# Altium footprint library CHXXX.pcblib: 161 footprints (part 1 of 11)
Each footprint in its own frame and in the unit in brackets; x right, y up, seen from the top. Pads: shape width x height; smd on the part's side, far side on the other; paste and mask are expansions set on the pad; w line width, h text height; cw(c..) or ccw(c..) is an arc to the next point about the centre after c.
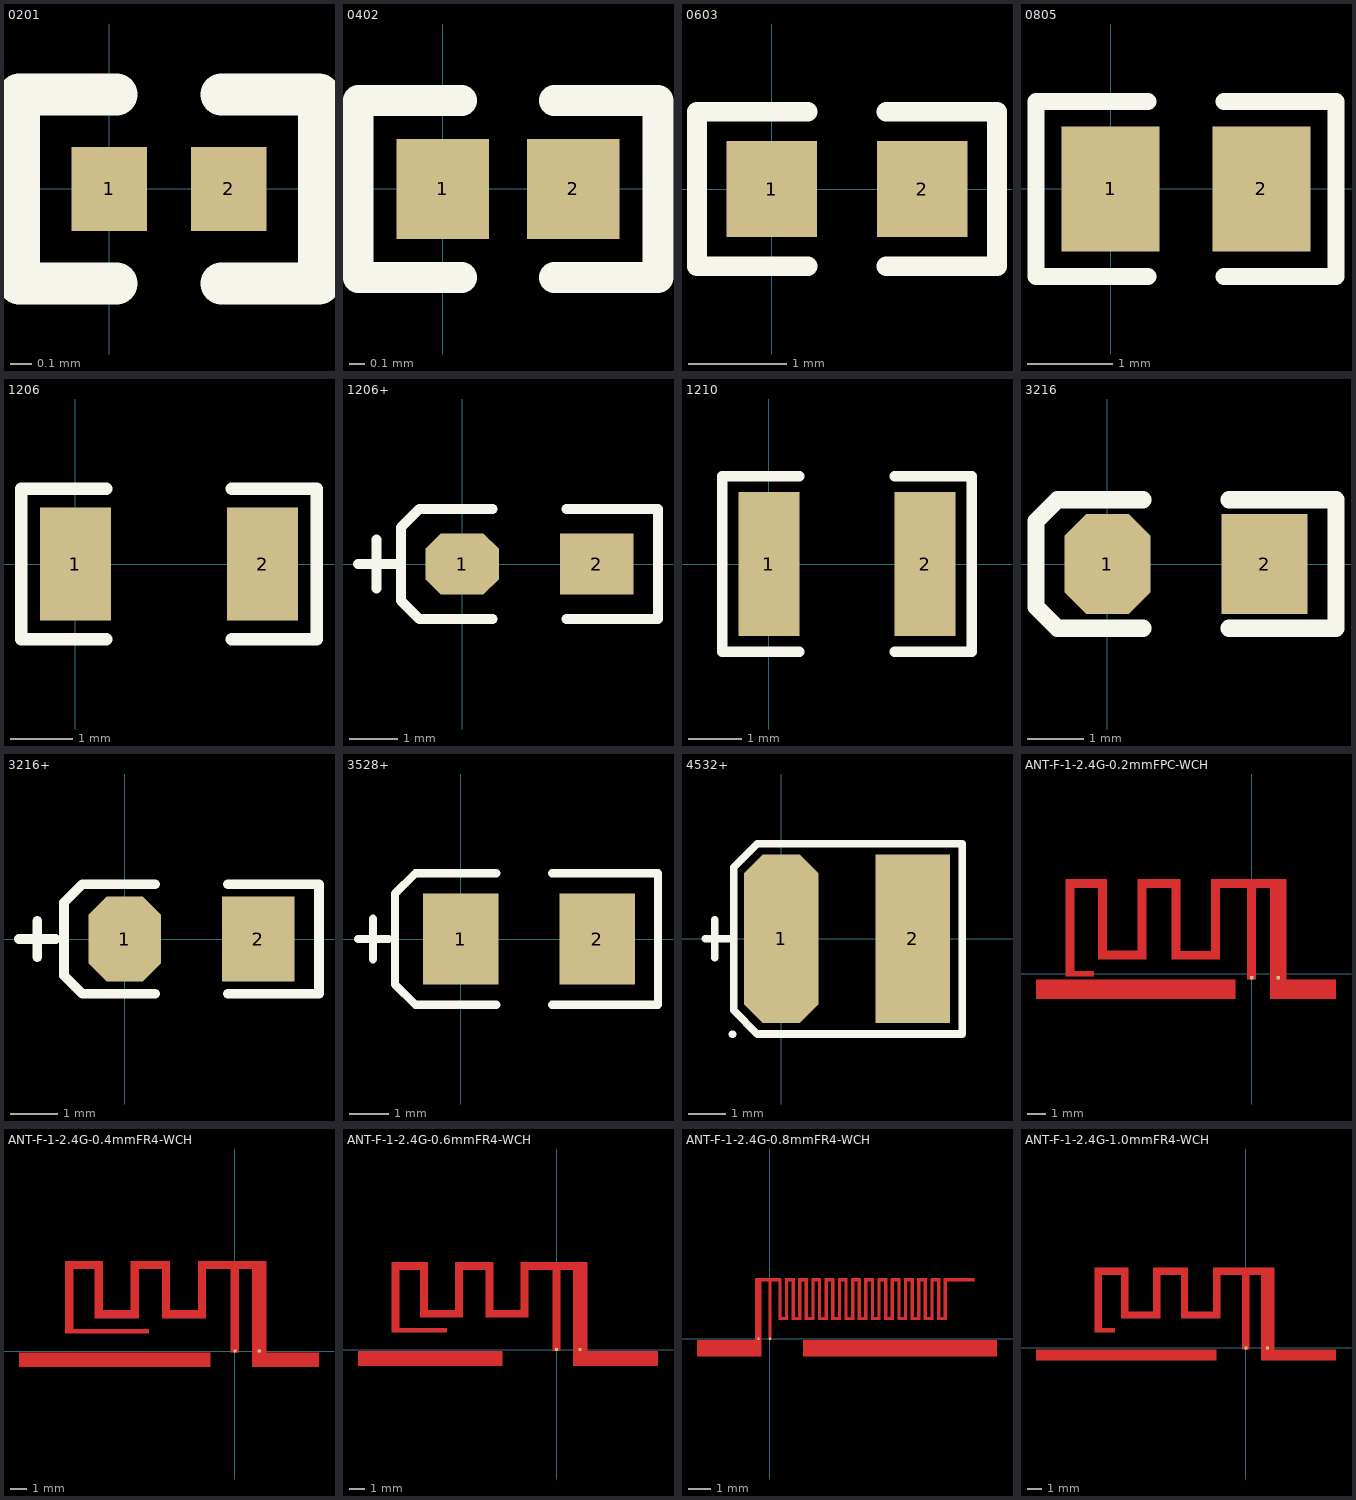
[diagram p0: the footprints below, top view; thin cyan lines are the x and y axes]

## 0201 [mm]
pads (2):
  rect 0.36x0.4 smd mask+0.051: 1(0,0) 2(0.57,0)
TopOverlay:
  lines w0.2: 0.035,-0.45 -0.43,-0.45 -0.43,0.45 0.035,0.45 ; 0.535,-0.45 1,-0.45 1,0.45 0.535,0.45

## 0402 [mm]
pads (2):
  rect 0.6x0.65 smd mask+0.051: 1(0,0) 2(0.85,0)
TopOverlay:
  lines w0.2: 0.125,-0.575 -0.55,-0.575 -0.55,0.575 0.125,0.575 ; 0.725,-0.575 1.4,-0.575 1.4,0.575 0.725,0.575

## 0603 [mm]
pads (2):
  rect 0.93x0.98 smd: 1(0,0) 2(1.54,0)
TopOverlay:
  lines w0.2: 0.37,-0.79 -0.765,-0.79 -0.765,0.79 0.37,0.79 ; 1.17,-0.79 2.305,-0.79 2.305,0.79 1.17,0.79

## 0805 [mm]
pads (2):
  rect 1.16x1.47 smd: 1(0,0) 2(1.78,0)
TopOverlay:
  lines w0.2: 0.44,-1.035 -0.88,-1.035 -0.88,1.035 0.44,1.035 ; 1.34,-1.035 2.66,-1.035 2.66,1.035 1.34,1.035

## 1206 [mm]
pads (2):
  rect 1.13x1.8 smd: 1(0,0) 2(2.98,0)
TopOverlay:
  lines w0.2: 0.49,-1.2 -0.865,-1.2 -0.865,1.2 0.49,1.2 ; 2.49,-1.2 3.845,-1.2 3.845,1.2 2.49,1.2

## 1206+ [mil]
pads (2):
  oct 60x50 smd: 1(0,0)
  rect 60x50 smd: 2(110,0)
TopOverlay:
  lines w8: -85,0 -50,0 ; -70,-20 -70,20 ; 25,-45 -35,-45 -50,-30 -50,30 -35,45 25,45 ; 85,-45 160,-45 160,45 85,45

## 1210 [mm]
pads (2):
  rect 1.16x2.72 smd: 1(0,0) 2(2.95,0)
TopOverlay:
  lines w0.2: 0.575,-1.66 -0.88,-1.66 -0.88,1.66 0.575,1.66 ; 2.375,-1.66 3.83,-1.66 3.83,1.66 2.375,1.66

## 3216 [mil]
pads (2):
  oct 60x70 smd: 1(0,0)
  rect 60x70 smd: 2(110,0)
TopOverlay:
  lines w12: 25,-45 -35,-45 -50,-30 -50,30 -35,45 25,45 ; 85,-45 160,-45 160,45 85,45

## 3216+ [mil]
pads (2):
  oct 60x70 smd: 1(0,0)
  rect 60x70 smd: 2(110,0)
TopOverlay:
  lines w8: -87.09,0 -57.09,0 ; -71.97,-15 -71.97,15 ; 25,-45 -35,-45 -50,-30 -50,30 -35,45 25,45 ; 85,-45 160,-45 160,45 85,45

## 3528+ [mil]
pads (2):
  rect 75x90 smd: 1(0,0) 2(135,0)
TopOverlay:
  lines w8: -101.69,0 -71.69,0 ; -86.97,-20 -86.97,20 ; 35,-65 -45,-65 -65,-45 -65,45 -45,65 35,65 ; 90,-65 195,-65 195,65 90,65

## 4532+ [mil]
pads (2):
  oct 78x177 smd: 1(0,0)
  rect 78x177 smd: 2(138,0)
TopOverlay:
  lines w8: -80,0 -50,0 ; -70,-20 -70,20 ; -51.18,-100.39 -51.18,-100.39 ; -50,-75 -25,-100 190,-100 190,100 -25,100 -50,75 -50,-75

## ANT-F-1-2.4G-0.2mmFPC-WCH [mm]
pads (2):
  rect 0.2x0.2 smd mask+0: 0(1.483,-0.204) 1(0,-0.204)
TopLayer:
  rectangle: -12,-1.4 -0.9,-0.304
  rectangle: 1.04,-1.4 4.7,-0.304
  rectangle: -10.36,-0.144 -8.76,0.156
  region: 0.24,5.027 -0.26,5.027 -0.26,-0.304 0.24,-0.304
  region: 1.94,5.296 1.04,5.296 1.04,-0.304 1.94,-0.304
  region: 1.94,5.296 -2.26,5.296 -2.26,4.796 1.94,4.796
  region: -1.76,5.296 -2.26,5.296 -2.26,0.796 -1.76,0.796
  region: -1.76,1.291 -4.46,1.291 -4.46,0.796 -1.76,0.796
  region: -3.96,5.296 -4.46,5.296 -4.46,0.796 -3.96,0.796
  region: -3.96,5.296 -6.36,5.296 -6.36,4.796 -3.96,4.796
  region: -5.86,5.296 -6.36,5.296 -6.36,0.796 -5.86,0.796
  region: -5.86,1.296 -8.56,1.296 -8.56,0.796 -5.86,0.796
  region: -8.06,5.296 -8.56,5.296 -8.56,0.796 -8.06,0.796
  region: -8.06,5.296 -10.36,5.296 -10.36,4.796 -8.06,4.796
  region: -9.86,5.296 -10.36,5.296 -10.36,-0.144 -9.86,-0.144
Mechanical13:
  text "适用FPC板材，0.2mm板厚，封装未开窗，建议天线开窗。技术咨询 tech@wch.cn" at -10.335,-3.328 h0.4
  text "GND" at 1.106,-1.729 h0.89
  text "GND" at -9.2,-1.729 h0.89

## ANT-F-1-2.4G-0.4mmFR4-WCH [mm]
pads (2):
  rect 0.2x0.2 smd mask+0: 0(1.483,0) 1(0,0)
TopLayer:
  rectangle: -13.183,-0.974 -1.488,-0.1
  rectangle: 1.04,-0.974 5.134,-0.1
  region: -9.86,5.18 -10.36,5.18 -10.36,1.06 -9.86,1.06
  region: -8.06,5.5 -10.36,5.5 -10.36,5 -8.06,5
  region: -8.06,5.18 -8.56,5.18 -8.56,2 -8.06,2
  region: -5.875,2.5 -8.364,2.5 -8.364,2 -5.875,2
  region: -5.86,5.18 -6.36,5.18 -6.36,2 -5.86,2
  region: -3.96,5.5 -6.36,5.5 -6.36,5 -3.96,5
  region: -3.96,5.18 -4.46,5.18 -4.46,2 -3.96,2
  region: -1.85,2.5 -4.39,2.5 -4.39,2 -1.85,2
  region: -1.76,5.18 -2.26,5.18 -2.26,2 -1.76,2
  region: 1.94,5.5 -2.26,5.5 -2.26,5 1.94,5
  region: 1.94,5.205 1.04,5.205 1.04,-0.1 1.94,-0.1
  region: 0.24,5.231 -0.26,5.231 -0.26,-0.1 0.24,-0.1
  region: -5.26,1.36 -10.36,1.36 -10.36,1.06 -5.26,1.06
Mechanical13:
  text "适用FR4板材，0.4mm板厚，封装未开窗，建议天线开窗。技术咨询 tech@wch.cn" at -10.901,-4.729 h0.4
  text "GND" at -9.2,-1.525 h0.89
  text "GND" at 1.106,-1.525 h0.89

## ANT-F-1-2.4G-0.6mmFR4-WCH [mm]
pads (2):
  rect 0.2x0.2 smd mask+0: 0(1.483,0) 1(0,0)
TopLayer:
  rectangle: -12.459,-1.031 -3.394,-0.1
  rectangle: 1.04,-1.031 6.37,-0.1
  region: -6.86,1.36 -10.36,1.36 -10.36,1.06 -6.86,1.06
  region: 0.24,5.231 -0.26,5.231 -0.26,-0.1 0.24,-0.1
  region: 1.94,5.205 1.04,5.205 1.04,-0.1 1.94,-0.1
  region: 1.94,5.5 -2.26,5.5 -2.26,5 1.94,5
  region: -1.76,5.18 -2.26,5.18 -2.26,2 -1.76,2
  region: -1.85,2.5 -4.39,2.5 -4.39,2 -1.85,2
  region: -3.96,5.18 -4.46,5.18 -4.46,2 -3.96,2
  region: -3.96,5.5 -6.36,5.5 -6.36,5 -3.96,5
  region: -5.86,5.18 -6.36,5.18 -6.36,2 -5.86,2
  region: -5.875,2.5 -8.364,2.5 -8.364,2 -5.875,2
  region: -8.06,5.18 -8.56,5.18 -8.56,2 -8.06,2
  region: -8.06,5.5 -10.36,5.5 -10.36,5 -8.06,5
  region: -9.86,5.18 -10.36,5.18 -10.36,1.06 -9.86,1.06
Mechanical13:
  text "GND" at -8.615,-1.863 h0.89
  text "GND" at 1.692,-1.863 h0.89
  text "适用FR4板材，0.6mm板厚，封装未开窗，建议天线开窗。技术咨询 tech@wch.cn" at -10.533,-5.177 h0.4

## ANT-F-1-2.4G-0.8mmFR4-WCH [mm]
pads (2):
  rect 0.1x0.1 smd mask+0: 0(-0.525,0) 1(0,0)
TopLayer:
  rectangle: -0.675,-0.05 -0.375,2.75
  rectangle: -0.075,-0.05 0.075,2.75
  region: 0.075,2.6 0.075,2.75 -0.675,2.75 -0.675,2.6
  rectangle: 0.375,0.85 0.525,2.75
  rectangle: 0.675,0.85 0.825,2.75
  rectangle: 0.975,0.85 1.125,2.75
  rectangle: 1.275,0.85 1.425,2.75
  rectangle: 1.575,0.85 1.725,2.75
  rectangle: 0.075,2.6 0.525,2.75
  rectangle: 0.675,2.6 1.125,2.75
  rectangle: 1.275,2.6 1.725,2.75
  rectangle: 0.375,0.85 0.825,1
  rectangle: 0.975,0.85 1.425,1
  rectangle: 2.175,0.85 2.625,1
  rectangle: 1.575,0.85 2.025,1
  rectangle: 2.475,2.6 2.925,2.75
  rectangle: 1.875,2.6 2.325,2.75
  rectangle: 2.775,0.85 2.925,2.75
  rectangle: 2.475,0.85 2.625,2.75
  rectangle: 2.175,0.85 2.325,2.75
  rectangle: 1.875,0.85 2.025,2.75
  rectangle: 3.375,0.85 3.825,1
  rectangle: 2.775,0.85 3.225,1
  rectangle: 3.675,2.6 4.125,2.75
  rectangle: 3.075,2.6 3.525,2.75
  rectangle: 3.975,0.85 4.125,2.75
  rectangle: 3.675,0.85 3.825,2.75
  rectangle: 3.375,0.85 3.525,2.75
  rectangle: 3.075,0.85 3.225,2.75
  rectangle: 4.575,0.85 5.025,1
  rectangle: 3.975,0.85 4.425,1
  rectangle: 4.875,2.6 5.325,2.75
  rectangle: 4.275,2.6 4.725,2.75
  rectangle: 5.175,0.85 5.325,2.75
  rectangle: 4.875,0.85 5.025,2.75
  rectangle: 4.575,0.85 4.725,2.75
  rectangle: 4.275,0.85 4.425,2.75
  rectangle: 5.775,0.85 6.225,1
  rectangle: 5.175,0.85 5.625,1
  rectangle: 6.075,2.6 6.525,2.75
  rectangle: 5.475,2.6 5.925,2.75
  rectangle: 6.375,0.85 6.525,2.75
  rectangle: 6.075,0.85 6.225,2.75
  rectangle: 5.775,0.85 5.925,2.75
  rectangle: 5.475,0.85 5.625,2.75
  rectangle: 6.975,0.85 7.425,1
  rectangle: 6.375,0.85 6.825,1
  rectangle: 7.275,2.6 7.725,2.75
  rectangle: 6.675,2.6 7.125,2.75
  rectangle: 7.575,0.85 7.725,2.75
  rectangle: 7.275,0.85 7.425,2.75
  rectangle: 6.975,0.85 7.125,2.75
  rectangle: 6.675,0.85 6.825,2.75
  rectangle: 7.575,0.85 8.025,1
  rectangle: 7.875,2.6 9.275,2.75
  rectangle: 7.875,0.85 8.025,2.75
  rectangle: 1.506,-0.797 10.3,-0.05
  rectangle: -3.312,-0.797 -0.375,-0.05
Mechanical13:
  text "GND" at 6.07,-1.419 h0.89
  text "GND" at -3.175,-1.419 h0.89
  text "适用FR4板材，0.8mm板厚，封装未开窗，建议天线开窗。技术咨询 tech@wch.cn" at -2.978,-4.128 h0.4

## ANT-F-1-2.4G-1.0mmFR4-WCH [mm]
pads (2):
  rect 0.2x0.2 smd mask+0: 0(1.483,0) 1(0,0)
TopLayer:
  region: -9.86,5.18 -10.36,5.18 -10.36,1.06 -9.86,1.06
  region: -8.06,5.5 -10.36,5.5 -10.36,5 -8.06,5
  region: -8.06,5.18 -8.56,5.18 -8.56,2 -8.06,2
  region: -5.875,2.5 -8.364,2.5 -8.364,2 -5.875,2
  region: -5.86,5.18 -6.36,5.18 -6.36,2 -5.86,2
  region: -3.96,5.5 -6.36,5.5 -6.36,5 -3.96,5
  region: -3.96,5.18 -4.46,5.18 -4.46,2 -3.96,2
  region: -1.85,2.5 -4.39,2.5 -4.39,2 -1.85,2
  region: -1.76,5.18 -2.26,5.18 -2.26,2 -1.76,2
  region: 1.94,5.5 -2.26,5.5 -2.26,5 1.94,5
  region: 1.94,5.205 1.04,5.205 1.04,-0.1 1.94,-0.1
  region: 0.24,5.231 -0.26,5.231 -0.26,-0.1 0.24,-0.1
  region: -8.96,1.36 -10.36,1.36 -10.36,1.06 -8.96,1.06
  rectangle: -14.378,-0.863 -2.035,-0.1
  rectangle: 1.04,-0.863 6.163,-0.1
Mechanical13:
  text "GND" at -8.427,-1.447 h0.89
  text "GND" at 1.88,-1.447 h0.89
  text "适用FR4板材，1.0mm板厚，封装未开窗，建议天线开窗。技术咨询 tech@wch.cn" at -10.487,-4.419 h0.4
